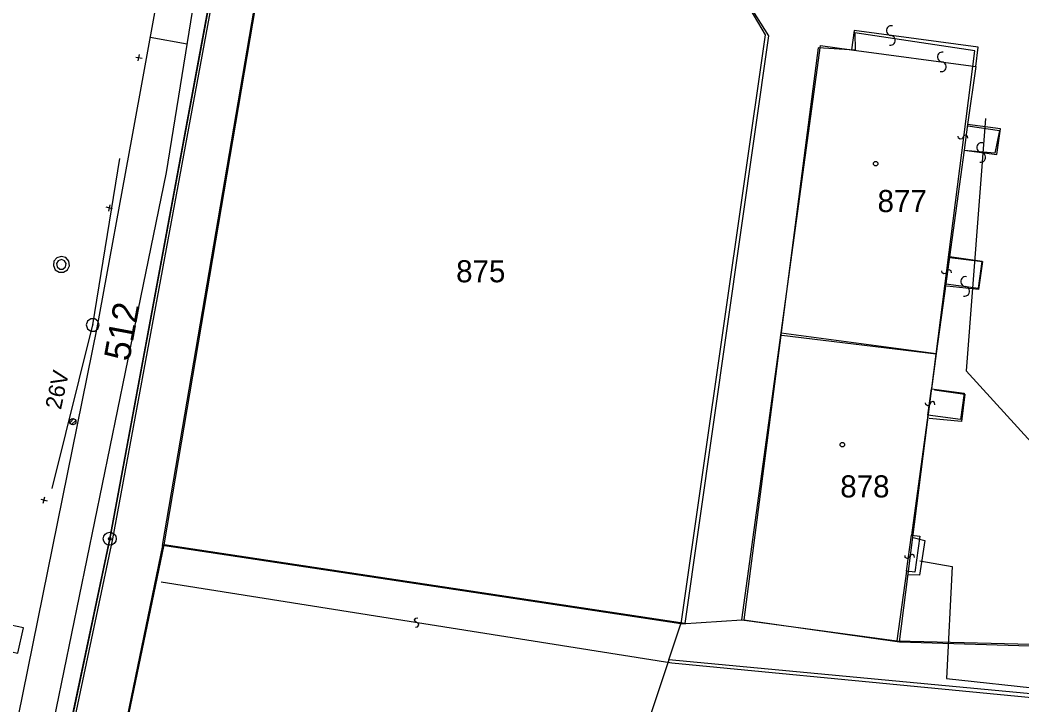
# Model space of a CAD drawing. Extents: x -469926 to -462499, y -1098642 to -1092733.
# Drawn here: x -465783.5 to -465706.3, y -1094774 to -1094721.3 of the extents above; entities that cross this region are included whole.
import ezdxf

# ---------------------------------------------------------------- set-up
doc = ezdxf.new("R2010")
doc.units = 0
for name, color, linetype in [('Vrstva 1', 7, 'Continuous'), ('Vrstva 10', 7, 'Continuous'), ('Vrstva 11', 7, 'Continuous'), ('Vrstva 14', 7, 'Continuous'), ('Vrstva 16', 7, 'Continuous'), ('Vrstva 24', 7, 'Continuous'), ('Vrstva 25', 7, 'Continuous'), ('Vrstva 27', 7, 'Continuous'), ('Vrstva 4', 7, 'Continuous'), ('Vrstva 50', 7, 'Continuous'), ('Vrstva 51', 7, 'Continuous'), ('Vrstva 63', 7, 'Continuous')]:
    doc.layers.add(name, color=color, linetype=linetype)

msp = doc.modelspace()

# ---------------------------------------------------------------- linework, layer by layer
at = {"layer": 'Vrstva 1'}
for p, q in [((-465776.58, -1094761.24), (-465767.15, -1094710.44)), ((-465776.58, -1094761.24), (-465767.15, -1094710.44)), ((-465772.52, -1094761.75), (-465763.82, -1094710.89)), ((-465772.52, -1094761.75), (-465763.82, -1094710.89)), ((-465730.19, -1094715.41), (-465726.08, -1094722.41)), ((-465730.19, -1094715.41), (-465726.08, -1094722.41)), ((-465726.08, -1094722.41), (-465732.58, -1094767.79)), ((-465726.08, -1094722.41), (-465732.58, -1094767.79)), ((-465727.88, -1094767.48), (-465724.85, -1094745.36)), ((-465727.88, -1094767.48), (-465724.85, -1094745.36)), ((-465724.85, -1094745.36), (-465712.9, -1094746.97)), ((-465724.85, -1094745.36), (-465712.9, -1094746.97)), ((-465712.9, -1094746.97), (-465713.27, -1094749.67)), ((-465712.9, -1094746.97), (-465713.27, -1094749.67)), ((-465713.27, -1094749.67), (-465710.74, -1094750.02)), ((-465713.27, -1094749.67), (-465710.74, -1094750.02)), ((-465710.74, -1094750.02), (-465711.02, -1094752.05)), ((-465710.74, -1094750.02), (-465711.02, -1094752.05)), ((-465713.55, -1094751.7), (-465714.81, -1094760.96)), ((-465713.55, -1094751.7), (-465714.81, -1094760.96)), ((-465711.02, -1094752.05), (-465713.55, -1094751.7)), ((-465711.02, -1094752.05), (-465713.55, -1094751.7)), ((-465789.35, -1094821.92), (-465776.58, -1094761.24)), ((-465714.81, -1094760.96), (-465714.17, -1094761.05)), ((-465714.81, -1094760.96), (-465714.17, -1094761.05)), ((-465714.17, -1094761.05), (-465714.55, -1094763.82)), ((-465714.17, -1094761.05), (-465714.55, -1094763.82)), ((-465772.52, -1094761.75), (-465815.93, -1094971.53)), ((-465732.58, -1094767.79), (-465772.52, -1094761.75)), ((-465732.58, -1094767.79), (-465772.52, -1094761.75)), ((-465715.19, -1094763.73), (-465715.93, -1094769.1)), ((-465715.19, -1094763.73), (-465715.93, -1094769.1)), ((-465714.55, -1094763.82), (-465715.19, -1094763.73)), ((-465714.55, -1094763.82), (-465715.19, -1094763.73)), ((-465732.58, -1094767.79), (-465727.88, -1094767.48)), ((-465732.58, -1094767.79), (-465727.88, -1094767.48)), ((-465727.88, -1094767.48), (-465715.93, -1094769.1)), ((-465727.88, -1094767.48), (-465715.93, -1094769.1)), ((-465733.51, -1094770.57), (-465732.58, -1094767.79)), ((-465733.51, -1094770.57), (-465732.58, -1094767.79)), ((-465715.93, -1094769.1), (-465690.76, -1094769.73)), ((-465715.93, -1094769.1), (-465690.76, -1094769.73)), ((-465733.51, -1094770.57), (-465736.68, -1094780.05)), ((-465733.51, -1094770.57), (-465736.68, -1094780.05)), ((-465692.74, -1094774.39), (-465733.51, -1094770.57)), ((-465692.74, -1094774.39), (-465733.51, -1094770.57))]:
    msp.add_line(p, q, dxfattribs=at)
at = {"layer": 'Vrstva 10'}
for points in [[(-465769.72, -1094568.39), (-465767.37, -1094578.26), (-465758.3, -1094583.1), (-465750.94, -1094593.18), (-465738.81, -1094611.42), (-465747.55, -1094611.11), (-465764.91, -1094609.35), (-465762, -1094648.91), (-465764.29, -1094695.06), (-465776.58, -1094761.24)], [(-465776.58, -1094761.24), (-465789.35, -1094821.92), (-465803.23, -1094885.69), (-465818.84, -1094962.75), (-465823.33, -1094981.25), (-465822.83, -1095013.45), (-465823.74, -1095017.71), (-465824.36, -1095023.1), (-465824.6, -1095025.22), (-465810.61, -1095029.56), (-465809.68, -1095029.85), (-465809.96, -1095030.97), (-465822.4, -1095064.82), (-465825.64, -1095073.83)]]:
    msp.add_lwpolyline(points, dxfattribs=at)
at = {"layer": 'Vrstva 11'}
for p, q in [((-465779.661, -1094752.304), (-465779.339, -1094751.981)), ((-465779.531, -1094752.439), (-465779.204, -1094752.112))]:
    msp.add_line(p, q, dxfattribs=at)
msp.add_circle((-465779.431, -1094752.212), 0.25, dxfattribs=at)
at = {"layer": 'Vrstva 14'}
for p, q in [((-465709.101, -1094728.853), (-465710.592, -1094748.288)), ((-465709.101, -1094728.853), (-465710.592, -1094748.288)), ((-465710.592, -1094748.288), (-465687.49, -1094773.704)), ((-465710.592, -1094748.288), (-465687.49, -1094773.704))]:
    msp.add_line(p, q, dxfattribs=at)
at = {"layer": 'Vrstva 16'}
for p, q in [((-465714.154, -1094762.928), (-465711.665, -1094763.382)), ((-465714.154, -1094762.928), (-465711.665, -1094763.382)), ((-465711.665, -1094763.382), (-465712.117, -1094772.008)), ((-465711.665, -1094763.382), (-465712.117, -1094772.008)), ((-465712.117, -1094772.008), (-465701.707, -1094773.143)), ((-465712.117, -1094772.008), (-465701.707, -1094773.143))]:
    msp.add_line(p, q, dxfattribs=at)
at = {"layer": 'Vrstva 24'}
for radius in [0.5, 0.5, 0.1, 0.1]:
    msp.add_circle((-465776.58, -1094761.24), radius, dxfattribs=at)
at = {"layer": 'Vrstva 25'}
for centre in [(-465717.57, -1094732.33), (-465717.57, -1094732.33), (-465720.13, -1094753.99), (-465720.13, -1094753.99)]:
    msp.add_circle(centre, 0.175, dxfattribs=at)
at = {"layer": 'Vrstva 27'}
msp.add_line((-465752.936, -1094767.695), (-465752.936, -1094767.695), dxfattribs=at)
msp.add_line((-465752.936, -1094767.695), (-465752.936, -1094767.695), dxfattribs=at)
for points in [[(-465772.609, -1094764.564), (-465733.275, -1094770.805)], [(-465772.609, -1094764.564), (-465733.275, -1094770.805)], [(-465753.018, -1094768.062), (-465752.862, -1094768.035), (-465752.776, -1094767.892), (-465752.827, -1094767.749), (-465753.052, -1094767.626), (-465753.09, -1094767.476), (-465753, -1094767.345), (-465752.853, -1094767.328)], [(-465753.018, -1094768.062), (-465752.862, -1094768.035), (-465752.776, -1094767.892), (-465752.827, -1094767.749), (-465753.052, -1094767.626), (-465753.09, -1094767.476), (-465753, -1094767.345), (-465752.853, -1094767.328)]]:
    msp.add_lwpolyline(points, dxfattribs=at)
at = {"layer": 'Vrstva 4'}
for p, q in [((-465719.23, -1094722.07), (-465719.43, -1094723.55)), ((-465719.23, -1094722.07), (-465719.43, -1094723.55)), ((-465709.67, -1094723.34), (-465719.23, -1094722.07)), ((-465709.67, -1094723.34), (-465719.23, -1094722.07)), ((-465724.85, -1094745.36), (-465721.82, -1094723.23)), ((-465724.85, -1094745.36), (-465721.82, -1094723.23)), ((-465721.82, -1094723.23), (-465719.43, -1094723.55)), ((-465721.82, -1094723.23), (-465719.43, -1094723.55)), ((-465719.43, -1094723.55), (-465709.86, -1094724.83)), ((-465719.43, -1094723.55), (-465709.86, -1094724.83)), ((-465709.86, -1094724.83), (-465709.67, -1094723.34)), ((-465709.86, -1094724.83), (-465709.67, -1094723.34)), ((-465709.86, -1094724.83), (-465710.48, -1094729.3)), ((-465709.86, -1094724.83), (-465710.48, -1094729.3)), ((-465710.48, -1094729.3), (-465710.75, -1094731.28)), ((-465710.48, -1094729.3), (-465710.75, -1094731.28)), ((-465707.95, -1094729.65), (-465710.48, -1094729.3)), ((-465707.95, -1094729.65), (-465710.48, -1094729.3)), ((-465708.22, -1094731.63), (-465707.95, -1094729.65)), ((-465708.22, -1094731.63), (-465707.95, -1094729.65)), ((-465710.75, -1094731.28), (-465711.88, -1094739.51)), ((-465710.75, -1094731.28), (-465711.88, -1094739.51)), ((-465710.75, -1094731.28), (-465708.22, -1094731.63)), ((-465710.75, -1094731.28), (-465708.22, -1094731.63)), ((-465711.88, -1094739.51), (-465712.16, -1094741.58)), ((-465711.88, -1094739.51), (-465712.16, -1094741.58)), ((-465709.35, -1094739.86), (-465711.88, -1094739.51)), ((-465709.35, -1094739.86), (-465711.88, -1094739.51)), ((-465709.64, -1094741.93), (-465709.35, -1094739.86)), ((-465709.64, -1094741.93), (-465709.35, -1094739.86)), ((-465712.16, -1094741.58), (-465712.9, -1094746.97)), ((-465712.16, -1094741.58), (-465712.9, -1094746.97)), ((-465712.16, -1094741.58), (-465709.64, -1094741.93)), ((-465712.16, -1094741.58), (-465709.64, -1094741.93)), ((-465713.55, -1094751.7), (-465713.27, -1094749.67)), ((-465713.55, -1094751.7), (-465713.27, -1094749.67)), ((-465715.19, -1094763.73), (-465714.81, -1094760.96)), ((-465715.19, -1094763.73), (-465714.81, -1094760.96))]:
    msp.add_line(p, q, dxfattribs=at)
at = {"layer": 'Vrstva 51'}
for centre, radius, start, end in [((-465716.357, -1094722.072), 0.376, 77.99036, 264.30149), ((-465716.357, -1094722.072), 0.376, 77.99036, 264.30149), ((-465716.428, -1094722.822), 0.377, 257.31432, 84.97753), ((-465716.428, -1094722.822), 0.377, 257.31432, 84.97753), ((-465712.435, -1094724.106), 0.376, 77.99036, 264.30149), ((-465712.435, -1094724.106), 0.376, 77.99036, 264.30149), ((-465712.505, -1094724.856), 0.377, 257.31432, 84.97753), ((-465712.505, -1094724.856), 0.377, 257.31432, 84.97753), ((-465709.396, -1094731.088), 0.376, 77.99036, 264.30149), ((-465709.396, -1094731.088), 0.376, 77.99036, 264.30149), ((-465709.467, -1094731.837), 0.377, 257.31432, 84.97753), ((-465709.467, -1094731.837), 0.377, 257.31432, 84.97753), ((-465710.641, -1094741.411), 0.376, 77.99036, 264.30149), ((-465710.641, -1094741.411), 0.376, 77.99036, 264.30149), ((-465710.711, -1094742.161), 0.377, 257.31432, 84.97753), ((-465710.711, -1094742.161), 0.377, 257.31432, 84.97753)]:
    msp.add_arc(centre, radius, start, end, dxfattribs=at)
at = {"layer": 'Vrstva 63'}
for p, q in [((-465774.581, -1094724.112), (-465774.088, -1094724.198)), ((-465774.581, -1094724.112), (-465774.088, -1094724.198)), ((-465774.378, -1094724.401), (-465774.292, -1094723.908)), ((-465774.378, -1094724.401), (-465774.292, -1094723.908)), ((-465774.335, -1094724.155), (-465774.335, -1094724.155)), ((-465774.335, -1094724.155), (-465774.335, -1094724.155)), ((-465710.832, -1094730.291), (-465710.832, -1094730.291)), ((-465710.832, -1094730.291), (-465710.832, -1094730.291)), ((-465776.377, -1094735.809), (-465776.864, -1094735.692)), ((-465776.377, -1094735.809), (-465776.864, -1094735.692)), ((-465776.562, -1094735.507), (-465776.679, -1094735.994)), ((-465776.562, -1094735.507), (-465776.679, -1094735.994)), ((-465776.621, -1094735.751), (-465776.621, -1094735.751)), ((-465776.621, -1094735.751), (-465776.621, -1094735.751)), ((-465780.308, -1094740.097), (-465780.308, -1094740.097)), ((-465780.308, -1094740.097), (-465780.308, -1094740.097)), ((-465712.099, -1094740.671), (-465712.099, -1094740.671)), ((-465712.099, -1094740.671), (-465712.099, -1094740.671)), ((-465777.89, -1094744.753), (-465777.89, -1094744.753)), ((-465777.89, -1094744.753), (-465777.89, -1094744.753)), ((-465713.365, -1094750.829), (-465713.365, -1094750.829)), ((-465713.365, -1094750.829), (-465713.365, -1094750.829)), ((-465781.884, -1094758.191), (-465781.396, -1094758.304)), ((-465781.884, -1094758.191), (-465781.396, -1094758.304)), ((-465781.696, -1094758.492), (-465781.583, -1094758.004)), ((-465781.696, -1094758.492), (-465781.583, -1094758.004)), ((-465781.64, -1094758.248), (-465781.64, -1094758.248)), ((-465781.64, -1094758.248), (-465781.64, -1094758.248)), ((-465714.933, -1094762.604), (-465714.933, -1094762.604)), ((-465714.933, -1094762.604), (-465714.933, -1094762.604))]:
    msp.add_line(p, q, dxfattribs=at)
for points in [[(-465764.647, -1094609.522), (-465761.804, -1094648.821), (-465764.137, -1094695.14), (-465776.359, -1094761.245), (-465789.187, -1094821.806), (-465803.567, -1094887.606), (-465823.432, -1094981.264), (-465822.703, -1095013.601)], [(-465765.567, -1094688.666), (-465765.693, -1094691.712), (-465767.651, -1094704.663), (-465772.234, -1094733.011), (-465774.797, -1094745.521), (-465782.481, -1094782.916), (-465790.926, -1094821.215), (-465799.259, -1094858.262), (-465809.214, -1094903.26), (-465815.719, -1094931.557), (-465821.039, -1094956.057), (-465824.781, -1094971.805), (-465830.549, -1095013.23)], [(-465815.768, -1094919.154), (-465811.433, -1094899.386), (-465798.014, -1094841.743), (-465792.768, -1094819.998), (-465777.545, -1094744.989), (-465774.863, -1094730.285), (-465771.11, -1094709.674)], [(-465815.804, -1094971.589), (-465797.448, -1094880.265), (-465785.161, -1094822.873), (-465772.395, -1094761.713), (-465763.787, -1094711.056)], [(-465730.263, -1094715.409), (-465725.825, -1094722.476), (-465732.281, -1094767.78)], [(-465730.263, -1094715.409), (-465725.825, -1094722.476), (-465732.281, -1094767.78)], [(-465773.461, -1094722.584), (-465770.61, -1094723.103)], [(-465773.461, -1094722.584), (-465770.61, -1094723.103)], [(-465719.171, -1094722.236), (-465719.146, -1094723.587), (-465722.003, -1094723.397), (-465727.731, -1094767.484), (-465715.734, -1094769.184), (-465709.933, -1094723.644)], [(-465719.171, -1094722.236), (-465719.146, -1094723.587), (-465722.003, -1094723.397), (-465727.731, -1094767.484), (-465715.734, -1094769.184), (-465709.933, -1094723.644)], [(-465709.933, -1094723.644), (-465719.171, -1094722.236)], [(-465709.933, -1094723.644), (-465719.171, -1094722.236)], [(-465715.734, -1094769.184), (-465690.638, -1094769.958), (-465684.695, -1094726.619), (-465675.26, -1094727.872), (-465675.524, -1094729.831), (-465673.27, -1094729.883), (-465678.795, -1094771.462), (-465690.638, -1094769.958)], [(-465715.734, -1094769.184), (-465690.638, -1094769.958), (-465684.695, -1094726.619), (-465675.26, -1094727.872), (-465675.524, -1094729.831), (-465673.27, -1094729.883), (-465678.795, -1094771.462), (-465690.638, -1094769.958)], [(-465710.475, -1094729.414), (-465708.015, -1094729.763), (-465708.383, -1094731.523), (-465710.74, -1094731.323)], [(-465710.475, -1094729.414), (-465708.015, -1094729.763), (-465708.383, -1094731.523), (-465710.74, -1094731.323)], [(-465710.463, -1094730.365), (-465710.493, -1094730.209), (-465710.638, -1094730.127), (-465710.78, -1094730.181), (-465710.898, -1094730.408), (-465711.047, -1094730.45), (-465711.18, -1094730.363), (-465711.2, -1094730.216)], [(-465710.463, -1094730.365), (-465710.493, -1094730.209), (-465710.638, -1094730.127), (-465710.78, -1094730.181), (-465710.898, -1094730.408), (-465711.047, -1094730.45), (-465711.18, -1094730.363), (-465711.2, -1094730.216)], [(-465781.009, -1094757.373), (-465777.89, -1094744.753), (-465775.795, -1094731.923)], [(-465781.009, -1094757.373), (-465777.89, -1094744.753), (-465775.795, -1094731.923)], [(-465780.31, -1094739.472), (-465780.65, -1094739.575), (-465780.877, -1094739.837), (-465780.924, -1094740.189), (-465780.774, -1094740.51), (-465780.485, -1094740.697), (-465780.13, -1094740.694), (-465779.84, -1094740.513), (-465779.691, -1094740.192), (-465779.74, -1094739.837), (-465779.971, -1094739.572), (-465780.31, -1094739.472)], [(-465780.31, -1094739.472), (-465780.65, -1094739.575), (-465780.877, -1094739.837), (-465780.924, -1094740.189), (-465780.774, -1094740.51), (-465780.485, -1094740.697), (-465780.13, -1094740.694), (-465779.84, -1094740.513), (-465779.691, -1094740.192), (-465779.74, -1094739.837), (-465779.971, -1094739.572), (-465780.31, -1094739.472)], [(-465780.306, -1094739.724), (-465780.549, -1094739.81), (-465780.678, -1094740.03), (-465780.632, -1094740.284), (-465780.432, -1094740.452), (-465780.181, -1094740.454), (-465779.984, -1094740.284), (-465779.94, -1094740.033), (-465780.064, -1094739.812), (-465780.308, -1094739.722)], [(-465780.306, -1094739.724), (-465780.549, -1094739.81), (-465780.678, -1094740.03), (-465780.632, -1094740.284), (-465780.432, -1094740.452), (-465780.181, -1094740.454), (-465779.984, -1094740.284), (-465779.94, -1094740.033), (-465780.064, -1094739.812), (-465780.308, -1094739.722)], [(-465711.857, -1094739.555), (-465709.327, -1094739.856), (-465709.637, -1094742.015), (-465712.095, -1094741.767)], [(-465711.857, -1094739.555), (-465709.327, -1094739.856), (-465709.637, -1094742.015), (-465712.095, -1094741.767)], [(-465711.73, -1094740.745), (-465711.76, -1094740.589), (-465711.905, -1094740.507), (-465712.047, -1094740.561), (-465712.165, -1094740.788), (-465712.314, -1094740.83), (-465712.447, -1094740.743), (-465712.467, -1094740.596)], [(-465711.73, -1094740.745), (-465711.76, -1094740.589), (-465711.905, -1094740.507), (-465712.047, -1094740.561), (-465712.165, -1094740.788), (-465712.314, -1094740.83), (-465712.447, -1094740.743), (-465712.467, -1094740.596)], [(-465778.04, -1094744.278), (-465778.294, -1094744.458), (-465778.39, -1094744.753), (-465778.296, -1094745.048), (-465778.04, -1094745.228), (-465777.74, -1094745.228), (-465777.487, -1094745.05), (-465777.39, -1094744.753), (-465777.484, -1094744.461), (-465777.736, -1094744.28), (-465778.04, -1094744.278)], [(-465778.04, -1094744.278), (-465778.294, -1094744.458), (-465778.39, -1094744.753), (-465778.296, -1094745.048), (-465778.04, -1094745.228), (-465777.74, -1094745.228), (-465777.487, -1094745.05), (-465777.39, -1094744.753), (-465777.484, -1094744.461), (-465777.736, -1094744.28), (-465778.04, -1094744.278)], [(-465777.89, -1094744.728), (-465777.915, -1094744.778), (-465777.865, -1094744.778), (-465777.89, -1094744.728)], [(-465777.89, -1094744.728), (-465777.915, -1094744.778), (-465777.865, -1094744.778), (-465777.89, -1094744.728)], [(-465724.79, -1094745.539), (-465712.898, -1094746.991)], [(-465724.79, -1094745.539), (-465712.898, -1094746.991)], [(-465713.046, -1094749.749), (-465710.686, -1094750.1), (-465710.947, -1094752.208), (-465713.455, -1094751.961)], [(-465713.046, -1094749.749), (-465710.686, -1094750.1), (-465710.947, -1094752.208), (-465713.455, -1094751.961)], [(-465712.996, -1094750.903), (-465713.026, -1094750.747), (-465713.171, -1094750.665), (-465713.313, -1094750.719), (-465713.431, -1094750.946), (-465713.58, -1094750.988), (-465713.713, -1094750.901), (-465713.733, -1094750.754)], [(-465712.996, -1094750.903), (-465713.026, -1094750.747), (-465713.171, -1094750.665), (-465713.313, -1094750.719), (-465713.431, -1094750.946), (-465713.58, -1094750.988), (-465713.713, -1094750.901), (-465713.733, -1094750.754)], [(-465714.684, -1094761.15), (-465713.787, -1094761.377), (-465714.179, -1094764.044), (-465715.03, -1094764.012)], [(-465714.684, -1094761.15), (-465713.787, -1094761.377), (-465714.179, -1094764.044), (-465715.03, -1094764.012)], [(-465732.281, -1094767.78), (-465772.395, -1094761.713)], [(-465732.281, -1094767.78), (-465772.395, -1094761.713)], [(-465714.564, -1094762.678), (-465714.594, -1094762.522), (-465714.739, -1094762.44), (-465714.881, -1094762.494), (-465714.999, -1094762.721), (-465715.148, -1094762.763), (-465715.281, -1094762.676), (-465715.301, -1094762.529)], [(-465714.564, -1094762.678), (-465714.594, -1094762.522), (-465714.739, -1094762.44), (-465714.881, -1094762.494), (-465714.999, -1094762.721), (-465715.148, -1094762.763), (-465715.281, -1094762.676), (-465715.301, -1094762.529)], [(-465784.381, -1094770.924), (-465784.161, -1094769.948), (-465783.673, -1094770.058), (-465783.233, -1094768.107), (-465784.208, -1094767.887), (-465784.649, -1094769.838), (-465784.161, -1094769.948)], [(-465733.275, -1094770.805), (-465692.751, -1094774.71), (-465673.295, -1094800.34), (-465652.159, -1094843.41), (-465643.795, -1094853.605)]]:
    msp.add_lwpolyline(points, dxfattribs=at)

# ---------------------------------------------------------------- texts
at = {"layer": 'Vrstva 11'}
msp.add_text('26V', height=1.25, rotation=77.7459, dxfattribs=at).set_placement((-465780.342, -1094751.338))
at = {"layer": 'Vrstva 50'}
for s, p in [('877', (-465717.421, -1094736.06)), ('875', (-465749.89, -1094741.47)), ('878', (-465720.294, -1094758.05))]:
    msp.add_text(s, height=1.7, dxfattribs=at).set_placement(p)
at = {"layer": 'Vrstva 63'}
msp.add_text('512', height=2, rotation=79.524, dxfattribs=at).set_placement((-465775.075, -1094747.621))
msp.add_text('512', height=2, rotation=79.524, dxfattribs=at).set_placement((-465775.075, -1094747.621))

doc.saveas('drawing.dxf')
